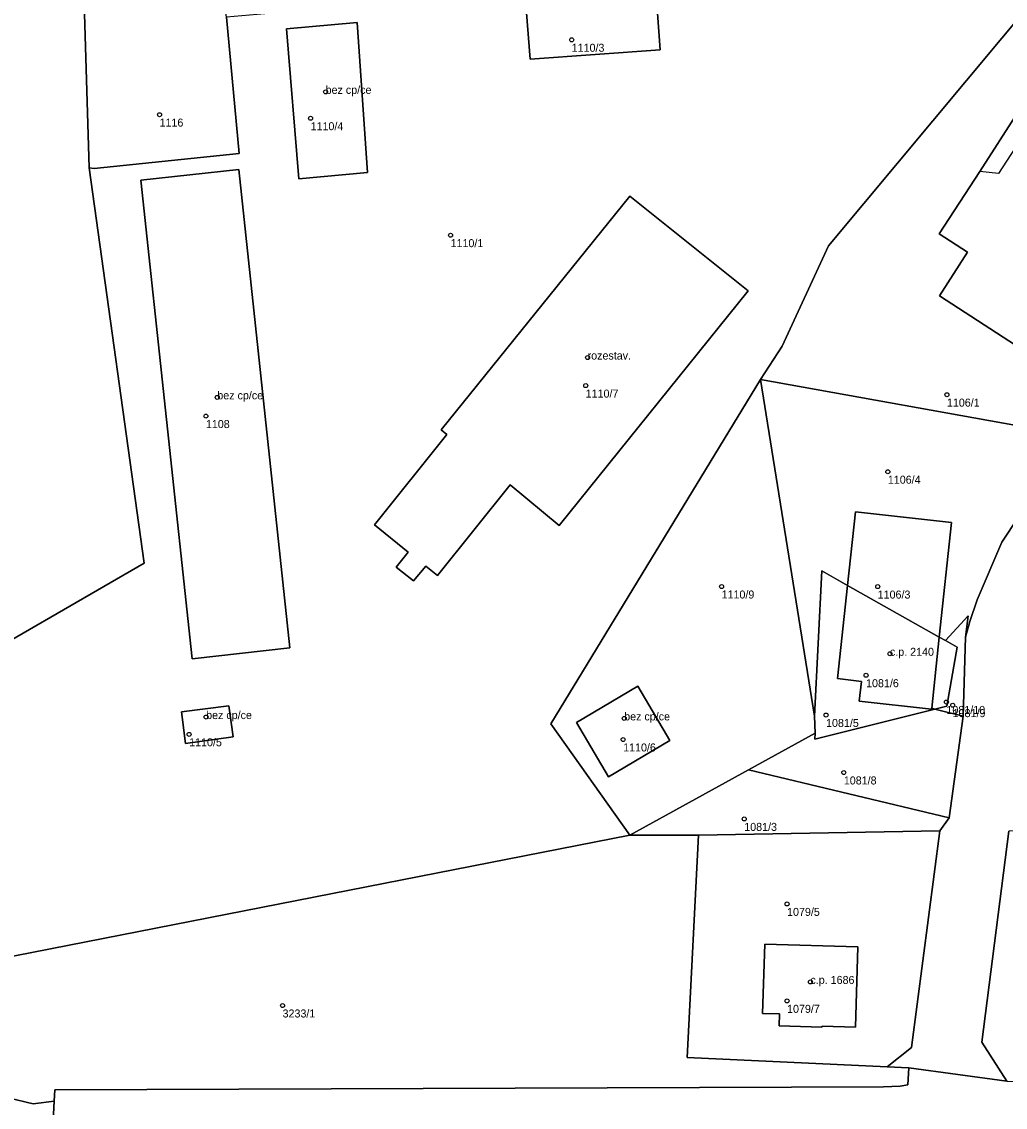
# Model space of a CAD drawing. Extents: x -878211 to -870363, y -1058464 to -1052522.
# Drawn here: x -875263.2 to -875140.3, y -1056535.5 to -1056399.9 of the extents above; entities that cross this region are included whole.
import ezdxf

# ---------------------------------------------------------------- set-up
doc = ezdxf.new("R2010")
doc.units = 0
for name, color, linetype in [('Vrstva 50', 7, 'Continuous'), ('Vrstva 51', 7, 'Continuous'), ('Vrstva 52', 7, 'Continuous')]:
    doc.layers.add(name, color=color, linetype=linetype)

msp = doc.modelspace()

# ---------------------------------------------------------------- linework, layer by layer
at = {"layer": 'Vrstva 50'}
for centre in [(-875194.45, -1056402.13994), (-875225.19, -1056408.63994), (-875245.94, -1056411.48994), (-875227.07, -1056411.93994), (-875209.58, -1056426.54994), (-875192.46, -1056441.82994), (-875192.7, -1056445.33994), (-875238.72, -1056446.79994), (-875147.57, -1056446.46994), (-875240.15, -1056449.14994), (-875154.95, -1056456.09994), (-875175.72, -1056470.43994), (-875156.22, -1056470.44994), (-875154.69, -1056478.83994), (-875157.67, -1056481.51994), (-875147.63, -1056484.85994), (-875146.85, -1056485.25994), (-875240.12, -1056486.73994), (-875187.89, -1056486.90994), (-875162.67, -1056486.48994), (-875242.24, -1056488.89994), (-875188.02, -1056489.54994), (-875160.45, -1056493.66994), (-875172.89, -1056499.46994), (-875167.54, -1056510.08994), (-875164.62, -1056519.82994), (-875167.54, -1056522.19994), (-875230.57, -1056522.77994)]:
    msp.add_circle(centre, 0.25, dxfattribs=at)
at = {"layer": 'Vrstva 51'}
for points in [[(-875200.57, -1056396.01), (-875217.64, -1056397.55), (-875227.04, -1056398.38), (-875237.58, -1056399.31), (-875235.99, -1056416.34), (-875254.11, -1056418.23), (-875254.73, -1056418.15), (-875247.86, -1056467.52), (-875278.14, -1056485.01), (-875275.46, -1056496.62), (-875270.88, -1056517.13), (-875266.18, -1056516.99), (-875187.17, -1056501.5), (-875197.07, -1056487.59), (-875170.85, -1056444.56), (-875168.16, -1056440.42), (-875162.37, -1056427.89), (-875132.07, -1056391.57), (-875148.79, -1056381.04), (-875152.82, -1056377.86), (-875169.32, -1056371.19), (-875186.95, -1056368.75), (-875185.58, -1056394.58)], [(-875297.94, -1056375.24), (-875296.47, -1056396.84), (-875295.85, -1056405.83), (-875294.84, -1056413.39), (-875292.37, -1056431.96), (-875291.77, -1056434.18), (-875286.31, -1056454.45), (-875279.8, -1056478.61), (-875278.14, -1056485.01), (-875247.86, -1056467.52), (-875254.73, -1056418.15), (-875255.37, -1056397.51), (-875264.75, -1056397.58), (-875264.81, -1056401.05), (-875273.11, -1056403.73), (-875273.73, -1056394.11), (-875281.75, -1056394.73), (-875282.44, -1056384.73), (-875274.36, -1056384.05), (-875273.77, -1056382.32), (-875274.48, -1056373.73), (-875274.52, -1056372.72)], [(-875129.04, -1056388.07), (-875132.07, -1056391.57), (-875162.37, -1056427.89), (-875168.16, -1056440.42), (-875170.85, -1056444.56), (-875135.15, -1056450.99), (-875133.69, -1056451.25), (-875120.69, -1056432.42), (-875116.47, -1056426.87), (-875108.15, -1056409.44), (-875104.53, -1056401.78), (-875104.23, -1056399.79)], [(-875255.37, -1056397.51), (-875254.73, -1056418.15), (-875254.11, -1056418.23), (-875235.99, -1056416.34), (-875237.58, -1056399.31), (-875238.21, -1056394.43), (-875247.88, -1056395.25), (-875255.43, -1056395.53)], [(-875183.93, -1056395.9), (-875200.2, -1056397.17), (-875199.65, -1056404.55), (-875183.4, -1056403.37)], [(-875183.93, -1056395.9), (-875183.4, -1056403.37), (-875199.65, -1056404.55), (-875200.2, -1056397.17)], [(-875219.94, -1056418.73), (-875228.54, -1056419.5), (-875230.08, -1056400.75), (-875221.26, -1056399.98)], [(-875219.94, -1056418.73), (-875221.26, -1056399.98), (-875230.08, -1056400.75), (-875228.54, -1056419.5)], [(-875138.74, -1056411.26), (-875143.46, -1056418.57), (-875148.53, -1056426.37), (-875145, -1056428.68), (-875148.49, -1056434.1), (-875136.62, -1056441.81), (-875132.83, -1056435.97), (-875133.94, -1056435.26), (-875126.55, -1056423.82), (-875125.44, -1056424.53), (-875117.47, -1056412.24), (-875124.37, -1056407.82), (-875125.1, -1056408.95), (-875133.71, -1056403.42)], [(-875138.74, -1056411.26), (-875133.71, -1056403.42), (-875125.1, -1056408.95), (-875124.37, -1056407.82), (-875117.47, -1056412.24), (-875125.44, -1056424.53), (-875126.55, -1056423.82), (-875133.94, -1056435.26), (-875132.83, -1056435.97), (-875136.62, -1056441.81), (-875148.49, -1056434.1), (-875145, -1056428.68), (-875148.53, -1056426.37), (-875143.46, -1056418.57)], [(-875241.85, -1056479.47), (-875229.67, -1056478.1), (-875236.05, -1056418.35), (-875248.29, -1056419.68)], [(-875241.85, -1056479.47), (-875248.29, -1056419.68), (-875236.05, -1056418.35), (-875229.67, -1056478.1)], [(-875172.42, -1056433.51), (-875187.17, -1056421.67), (-875210.77, -1056450.87), (-875210.05, -1056451.45), (-875219.08, -1056462.74), (-875214.86, -1056466.14), (-875216.36, -1056468), (-875214.22, -1056469.74), (-875212.68, -1056467.9), (-875211.22, -1056469.07), (-875202.13, -1056457.75), (-875196.03, -1056462.82)], [(-875172.42, -1056433.51), (-875196.03, -1056462.82), (-875202.13, -1056457.75), (-875211.22, -1056469.07), (-875212.68, -1056467.9), (-875214.22, -1056469.74), (-875216.36, -1056468), (-875214.86, -1056466.14), (-875219.08, -1056462.74), (-875210.05, -1056451.45), (-875210.77, -1056450.87), (-875187.17, -1056421.67)], [(-875164.05, -1056488.76), (-875164.1, -1056486.64), (-875170.85, -1056444.56), (-875197.07, -1056487.59), (-875187.17, -1056501.5), (-875172.36, -1056493.34)], [(-875170.85, -1056444.56), (-875164.1, -1056486.64), (-875163.2, -1056468.48), (-875159.98, -1056470.3), (-875158.97, -1056461.12), (-875146.99, -1056462.43), (-875148.52, -1056476.76), (-875147.76, -1056477.19), (-875144.9, -1056474.09), (-875145.24, -1056476.77), (-875144.72, -1056474.82), (-875143.78, -1056472.1), (-875140.71, -1056464.89), (-875134.44, -1056455.41), (-875133.69, -1056451.25), (-875135.15, -1056450.99)], [(-875148.52, -1056476.76), (-875146.99, -1056462.43), (-875158.97, -1056461.12), (-875159.98, -1056470.3)], [(-875164.1, -1056486.64), (-875164.05, -1056488.76), (-875164.08, -1056489.51), (-875149.07, -1056485.74), (-875149.47, -1056485.64), (-875149.48, -1056485.77), (-875158.52, -1056484.77), (-875158.26, -1056482.28), (-875161.25, -1056481.94), (-875159.98, -1056470.3), (-875163.2, -1056468.48)], [(-875148.52, -1056476.76), (-875159.98, -1056470.3), (-875161.25, -1056481.94), (-875158.26, -1056482.28), (-875158.52, -1056484.77), (-875149.48, -1056485.77), (-875149.47, -1056485.64)], [(-875144.9, -1056474.09), (-875147.76, -1056477.19), (-875146.29, -1056478.02), (-875147.59, -1056485.37), (-875149.07, -1056485.74), (-875145.56, -1056486.62), (-875145.24, -1056476.77)], [(-875147.76, -1056477.19), (-875148.52, -1056476.76), (-875149.47, -1056485.64), (-875149.07, -1056485.74), (-875147.59, -1056485.37), (-875146.29, -1056478.02)], [(-875186.19, -1056482.88), (-875193.85, -1056487.4), (-875189.83, -1056494.2), (-875182.17, -1056489.67)], [(-875186.19, -1056482.88), (-875182.17, -1056489.67), (-875189.83, -1056494.2), (-875193.85, -1056487.4)], [(-875237.29, -1056485.34), (-875243.18, -1056486.09), (-875242.69, -1056490.03), (-875236.76, -1056489.21)], [(-875237.29, -1056485.34), (-875236.76, -1056489.21), (-875242.69, -1056490.03), (-875243.18, -1056486.09)], [(-875164.05, -1056488.76), (-875172.36, -1056493.34), (-875147.28, -1056499.31), (-875145.56, -1056486.62), (-875149.07, -1056485.74), (-875164.08, -1056489.51)], [(-875187.17, -1056501.5), (-875178.61, -1056501.49), (-875148.45, -1056500.97), (-875147.28, -1056499.31), (-875172.36, -1056493.34)], [(-875259.1, -1056534.73), (-875259.02, -1056533.3), (-875155.48, -1056532.95), (-875153.43, -1056532.87), (-875152.44, -1056532.68), (-875152.33, -1056530.58), (-875155.05, -1056530.45), (-875180.03, -1056529.27), (-875178.61, -1056501.49), (-875187.17, -1056501.5), (-875266.18, -1056516.99), (-875270.88, -1056517.13), (-875266.97, -1056533.79), (-875261.72, -1056535.04)], [(-875155.05, -1056530.45), (-875151.99, -1056528.03), (-875148.45, -1056500.97), (-875178.61, -1056501.49), (-875180.03, -1056529.27)], [(-875139.84, -1056500.98), (-875143.21, -1056527.35), (-875140.1, -1056532.21), (-875118.8, -1056532.29), (-875118.14, -1056517.12), (-875117.42, -1056500.79)], [(-875163.17, -1056525.34), (-875163.18, -1056525.49), (-875168.52, -1056525.3), (-875168.47, -1056523.83), (-875170.59, -1056523.77), (-875170.32, -1056515.1), (-875158.7, -1056515.43), (-875159.01, -1056525.47)], [(-875163.17, -1056525.34), (-875159.01, -1056525.47), (-875158.7, -1056515.43), (-875170.32, -1056515.1), (-875170.59, -1056523.77), (-875168.47, -1056523.83), (-875168.52, -1056525.3), (-875163.18, -1056525.49)], [(-875259.22, -1056537.17), (-875259.1, -1056534.73), (-875261.72, -1056535.04), (-875266.97, -1056533.79), (-875267.96, -1056540.29), (-875281.72, -1056541.28), (-875296.54, -1056543.51), (-875313.42, -1056546.47), (-875315.41, -1056546.95), (-875303.53, -1056568.52), (-875300.73, -1056568.5), (-875300.61, -1056561.1), (-875300.43, -1056549.82), (-875291.04, -1056550.02), (-875290.97, -1056547.29), (-875290.97, -1056544.03), (-875271.64, -1056543.49), (-875236.37, -1056544.34), (-875236.32, -1056541.49), (-875236.79, -1056539.65), (-875237.65, -1056538.66)]]:
    msp.add_lwpolyline(points, close=True, dxfattribs=at)
for points in [[(-875134.44, -1056455.41), (-875140.71, -1056464.89), (-875143.78, -1056472.1), (-875144.72, -1056474.82), (-875145.24, -1056476.77), (-875145.56, -1056486.62), (-875147.28, -1056499.31), (-875148.45, -1056500.97), (-875151.99, -1056528.03), (-875155.05, -1056530.45), (-875152.33, -1056530.58), (-875140.1, -1056532.21), (-875143.21, -1056527.35), (-875139.84, -1056500.98)], [(-875140.1, -1056532.21), (-875152.33, -1056530.58), (-875152.44, -1056532.68), (-875153.43, -1056532.87), (-875155.48, -1056532.95), (-875259.02, -1056533.3), (-875259.1, -1056534.73), (-875259.22, -1056537.17), (-875237.65, -1056538.66), (-875221.97, -1056538.9), (-875180.65, -1056538.78), (-875165.42, -1056538.58), (-875111.86, -1056538.46)]]:
    msp.add_lwpolyline(points, dxfattribs=at)
at = {"layer": 'Vrstva 52'}
for points in [[(-875183.93, -1056395.9), (-875200.2, -1056397.17), (-875199.65, -1056404.55), (-875183.4, -1056403.37)], [(-875228.54, -1056419.5), (-875219.94, -1056418.73), (-875221.26, -1056399.98), (-875230.08, -1056400.75)], [(-875148.53, -1056426.37), (-875145, -1056428.68), (-875148.49, -1056434.1), (-875136.62, -1056441.81), (-875132.83, -1056435.97), (-875133.94, -1056435.26), (-875126.55, -1056423.82), (-875125.44, -1056424.53), (-875117.47, -1056412.24), (-875124.37, -1056407.82), (-875125.1, -1056408.95), (-875133.71, -1056403.42), (-875138.74, -1056411.26), (-875137.49, -1056413.25), (-875141.12, -1056418.85), (-875143.46, -1056418.57)], [(-875236.05, -1056418.35), (-875248.29, -1056419.68), (-875241.85, -1056479.47), (-875229.67, -1056478.1)], [(-875210.77, -1056450.87), (-875210.05, -1056451.45), (-875219.08, -1056462.74), (-875214.86, -1056466.14), (-875216.36, -1056468), (-875214.22, -1056469.74), (-875212.68, -1056467.9), (-875211.22, -1056469.07), (-875202.13, -1056457.75), (-875196.03, -1056462.82), (-875172.42, -1056433.51), (-875187.17, -1056421.67)], [(-875149.47, -1056485.64), (-875148.52, -1056476.76), (-875146.99, -1056462.43), (-875158.97, -1056461.12), (-875159.98, -1056470.3), (-875161.25, -1056481.94), (-875158.26, -1056482.28), (-875158.52, -1056484.77), (-875149.48, -1056485.77)], [(-875186.19, -1056482.88), (-875193.85, -1056487.4), (-875189.83, -1056494.2), (-875182.17, -1056489.67)], [(-875237.29, -1056485.34), (-875243.18, -1056486.09), (-875242.69, -1056490.03), (-875236.76, -1056489.21)], [(-875170.59, -1056523.77), (-875168.47, -1056523.83), (-875168.52, -1056525.3), (-875163.18, -1056525.49), (-875163.17, -1056525.34), (-875159.01, -1056525.47), (-875158.7, -1056515.43), (-875170.32, -1056515.1)]]:
    msp.add_lwpolyline(points, close=True, dxfattribs=at)

# ---------------------------------------------------------------- texts
at = {"layer": 'Vrstva 50'}
for s, p in [('1110/3', (-875194.45, -1056403.629)), ('bez cp/ce', (-875225.19, -1056408.889)), ('1116', (-875245.94, -1056412.979)), ('1110/4', (-875227.07, -1056413.429)), ('1110/1', (-875209.58, -1056428.039)), ('rozestav.', (-875192.46, -1056442.08)), ('bez cp/ce', (-875238.72, -1056447.05)), ('1110/7', (-875192.7, -1056446.829)), ('1106/1', (-875147.57, -1056447.959)), ('1108', (-875240.15, -1056450.639)), ('1106/4', (-875154.95, -1056457.589)), ('1110/9', (-875175.72, -1056471.929)), ('1106/3', (-875156.22, -1056471.939)), ('c.p. 2140', (-875154.69, -1056479.09)), ('1081/6', (-875157.67, -1056483.009)), ('1081/10', (-875147.63, -1056486.349)), ('bez cp/ce', (-875240.12, -1056486.99)), ('bez cp/ce', (-875187.89, -1056487.159)), ('1081/9', (-875146.85, -1056486.749)), ('1081/5', (-875162.67, -1056487.979)), ('1110/5', (-875242.24, -1056490.389)), ('1110/6', (-875188.02, -1056491.039)), ('1081/8', (-875160.45, -1056495.159)), ('1081/3', (-875172.89, -1056500.959)), ('1079/5', (-875167.54, -1056511.579)), ('c.p. 1686', (-875164.62, -1056520.08)), ('3233/1', (-875230.57, -1056524.269)), ('1079/7', (-875167.54, -1056523.689))]:
    msp.add_text(s, height=0.999996, dxfattribs=at).set_placement(p)

doc.saveas('drawing.dxf')
